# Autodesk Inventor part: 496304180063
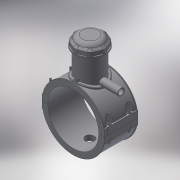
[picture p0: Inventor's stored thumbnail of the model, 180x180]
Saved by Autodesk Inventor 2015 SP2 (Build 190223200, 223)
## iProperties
Created: 2017-07
Part Number: 496304180063
Material: Generic
Description: PLASSON TAPPING SADDLE 180x63
Document SubType Name: Modeling
Designer: KIM
Mass: 1352.13 g
Surface Area: 2876.17 cm^2
Volume: 1352.13 cm^3
Density: 1 g/cm^3
Appearance: Default
Author: KIM
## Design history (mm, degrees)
derived "496304.ipt"
feature "Solid1::496304.ipt"
feature "Solid2::496304.ipt"
feature "Solid4::496304.ipt"
feature "Solid5::496304.ipt"
tag "TaggingFeature1"
body "Solid1"
body "Solid2"
other parameters: "B_" = 219, "L_" = 118, "d_t" = 6, "H_2" = 138, "d_1" = 63, "H_" = 197, "d1" = 205.2, "d148" = 2.7, "d160" = 2.7, "d169" = 3.375, "d192" = 6.3, "d2" = 219, "d3" = 45, "d4" = 118, "d5" = 0, "d6" = 0.1, "d8" = 0, "d19" = 6, "d20" = 6, "d21" = 70.8, "d23" = 0, "d24" = 35.4, "d26" = 0, "d29" = 3, "d31" = 6, "d32" = 0, "d33" = 0, "d34" = 0.6, "d40" = 106.704, "d41" = 75.6, "d43" = 0, "d45" = 0, "d47" = 173.4, "d70" = 15, "d72" = 0, "d73" = 6, "d75" = 5, "d76" = 0, "d77" = 9, "d79" = 15, "d80" = 47.2, "d82" = 5 deg, "d84" = 4, "d85" = 14, "d86" = 0, "d87" = 3, "d88" = 0, "d89" = 1, "d90" = 1, "d91" = 94.4, "d92" = 0, "d93" = 0.5, "d94" = 94.73684, "d96" = 209.304, "d97" = 2.36, "d98" = 0, "d102" = 1.8, "d120" = 140 deg, "d121" = 24.228, "d122" = 20 deg, "d123" = 410.4, "d124" = 123.12, "d126" = 0, "d143" = 185.4, "d145" = 19.38462, "d149" = 2.7, "d150" = 21.32308, "d153" = 118, "d154" = 0, "d156" = 102.6, "d157" = 160 deg, "d159" = 5.04, "d161" = 2.7, "d162" = 70.8, "d163" = 0, "d167" = 18, "d168" = 100.09756, "d170" = 3.375, "d172" = 0, "d173" = 1, "d176" = 20 deg, "d177" = 12.6, "d178" = 25.2, "d180" = 0, "d183" = 10.08, "d184" = 10.08, "d185" = 38.35, "d186" = 38.35, "d187" = 102.6, "d188" = 7.56, "d189" = 12.6, "d190" = 0, "d191" = 153.9, "d193" = 6.3, "d194" = 4.13, "d195" = 90 deg, "d197" = 0, "d199" = 0, "d200" = 12.6, "d202" = 0, "d203" = 138, "d204" = 71.82, "d205" = 52.92, "d206" = 64.26, "d207" = 103.5, "d208" = 107.64, "d209" = 128.34, "d210" = 65.016, "d211" = 75.6, "d212" = 60.48, "d213" = -10.35, "d216" = 0, "d217" = 18, "d218" = 18, "d219" = 3.6, "d224" = 0, "d230" = 3.6, "d233" = 6, "d236" = 109.5, "d237" = 35.4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
